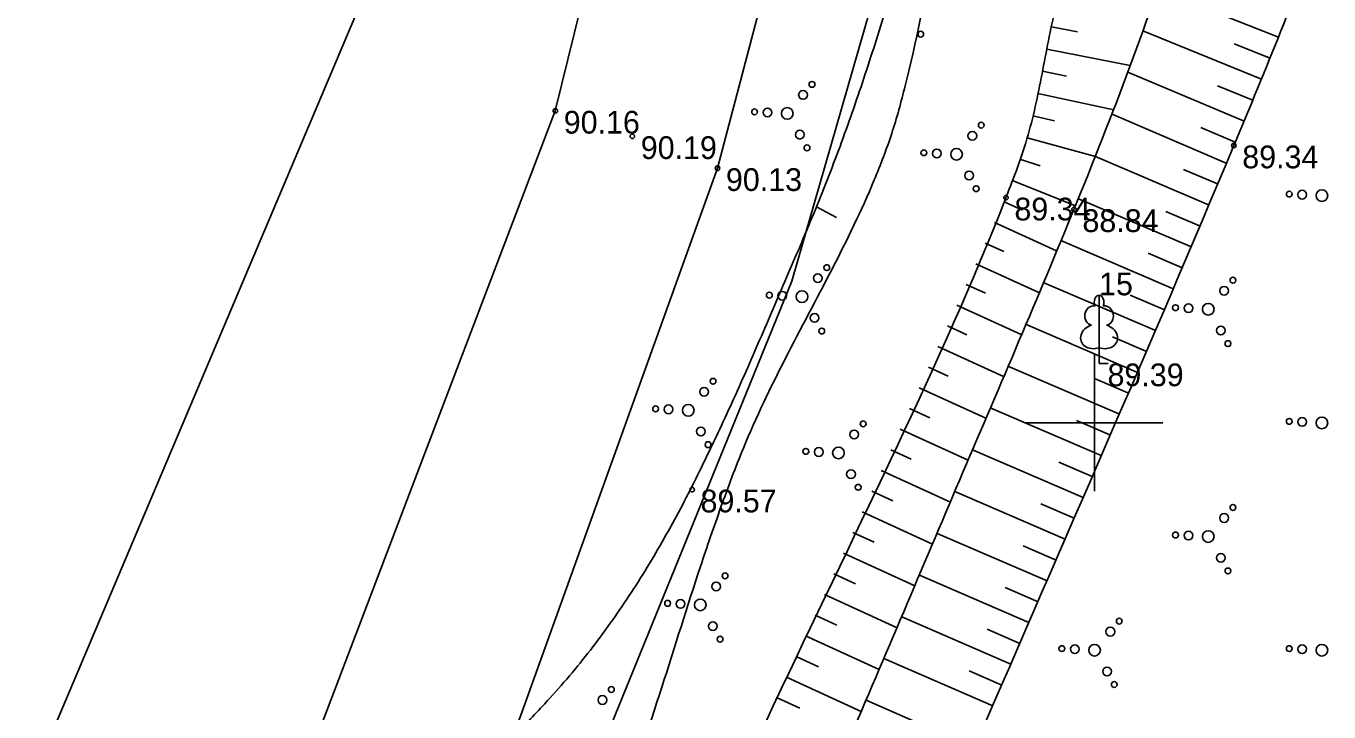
# Model space of a CAD drawing. Extents: x 635228 to 635525, y 248590 to 248800.
# Drawn here: x 635326.51 to 635355.15, y 248693.64 to 248708.73 of the extents above; entities that cross this region are included whole.
import ezdxf

# ---------------------------------------------------------------- set-up
doc = ezdxf.new("R2010")
doc.units = 0
for name, color, linetype in [('CELI_CMAL_####_####_#', 7, 'Continuous'), ('GEOD_ELEM_####_####_#', 7, 'Continuous'), ('RAMI_UZMR_####_####_#', 7, 'Continuous'), ('RELJ_AATZ_####_TKST_#', 7, 'Continuous'), ('RELJ_ELEM_####_####_#', 7, 'Continuous'), ('RELJ_HORZ_PAMT_####_#', 7, 'Continuous'), ('RELJ_HORZ_RESN_####_#', 7, 'Continuous'), ('RELJ_NOGA_####_####_#', 7, 'Continuous'), ('RELJ_NOGL_####_####_#', 7, 'Continuous'), ('ROBZ_PROJ_####_####_#', 7, 'Continuous'), ('ROBZ_UZMR_####_####_#', 7, 'Continuous'), ('TERT_DIAM_####_TKST_#', 7, 'Continuous'), ('TERT_ELEM_####_####_#', 7, 'Continuous'), ('TERT_KONT_####_####_#', 7, 'Continuous')]:
    doc.layers.add(name, color=color, linetype=linetype)

msp = doc.modelspace()

# ---------------------------------------------------------------- linework, layer by layer
at = {"layer": 'CELI_CMAL_####_####_#'}
for points in [[(635327.703, 248680.035), (635336.747, 248691.797), (635341.71, 248705.602), (635344.776, 248717.251), (635350.856, 248738.106), (635354.904, 248753.168), (635356.755, 248761.086), (635356.988, 248762.081)], [(635352.126, 248761.775), (635351.394, 248755.812), (635346.791, 248738.298), (635340.529, 248716.56), (635338.144, 248706.864), (635332.779, 248692.762), (635327.977, 248685.285), (635325.201, 248682.696)]]:
    msp.add_lwpolyline(points, dxfattribs=at)
at = {"layer": 'GEOD_ELEM_####_####_#'}
for p, q in [((635350, 248701.5), (635350, 248700)), ((635348.5, 248700), (635350, 248700)), ((635350, 248700), (635350, 248698.5)), ((635350, 248700), (635351.5, 248700))]:
    msp.add_line(p, q, dxfattribs=at)
at = {"layer": 'RAMI_UZMR_####_####_#'}
msp.add_lwpolyline([(635379.918, 248627.738), (635364.657, 248634.365), (635359.326, 248636.387), (635355.893, 248639.014), (635323.971, 248655.917), (635326.8, 248663.851), (635331.354, 248676.262), (635327.703, 248680.035), (635326.374, 248681.182), (635325.201, 248682.696), (635327.977, 248685.285), (635332.779, 248692.762), (635338.144, 248706.864), (635340.529, 248716.56), (635346.791, 248738.298), (635351.394, 248755.812), (635352.126, 248761.775)], dxfattribs=at)
at = {"layer": 'RELJ_ELEM_####_####_#'}
for centre in [(635338.144, 248706.864), (635339.838, 248706.305), (635353.063, 248706.101), (635341.71, 248705.602), (635348.053, 248704.954), (635349.548, 248704.698), (635349.55, 248704.699), (635341.152, 248698.532)]:
    msp.add_circle(centre, 0.05, dxfattribs=at)
at = {"layer": 'RELJ_HORZ_PAMT_####_#'}
msp.add_spline([(635330.297, 248677.354), (635331.177, 248678.319), (635332.06, 248679.489), (635332.793, 248680.772), (635333.481, 248682.089), (635334.226, 248683.36), (635335.284, 248684.77), (635336.431, 248686.125), (635337.538, 248687.508), (635338.035, 248688.237), (635338.472, 248689.004), (635339.583, 248691.554), (635340.487, 248694.188), (635341.335, 248696.84), (635341.787, 248698.153), (635342.281, 248699.447), (635343.206, 248701.423), (635344.222, 248703.369), (635345.157, 248705.345), (635345.54, 248706.364), (635345.837, 248707.412), (635346.445, 248710.352), (635346.944, 248713.307), (635347.835, 248719.233), (635348.116, 248721.113), (635348.378, 248722.995), (635348.645, 248724.878), (635348.937, 248726.758), (635349.503, 248728.159), (635350.332, 248729.539), (635351.235, 248730.852), (635351.672, 248731.412), (635352.153, 248731.934), (635352.67, 248732.415), (635353.216, 248732.849), (635353.585, 248732.808), (635353.973, 248732.393), (635354.375, 248731.871), (635354.581, 248731.654), (635354.79, 248731.511), (635355.514, 248731.162), (635356.357, 248730.815), (635357.156, 248730.69), (635357.748, 248731.008), (635358.207, 248731.666), (635358.657, 248732.33), (635359.531, 248733.675), (635361.193, 248736.42), (635362.771, 248739.216), (635364.301, 248742.038), (635372.089, 248756.526)], degree=3, dxfattribs=at)
at = {"layer": 'RELJ_HORZ_RESN_####_#'}
msp.add_line((635343.886, 248704.75), (635344.329, 248704.519), dxfattribs=at)
for points in [[(635346.739, 248717.915), (635346.608, 248716.083), (635346.466, 248714.252), (635346.348, 248713.214), (635346.269, 248712.697), (635346.182, 248712.182), (635345.98, 248711.16), (635345.727, 248710.151), (635345.266, 248708.625), (635344.77, 248707.113), (635344.229, 248705.619), (635343.634, 248704.146), (635343.044, 248702.77), (635342.451, 248701.393), (635341.838, 248700.031), (635341.518, 248699.356), (635341.19, 248698.685), (635340.494, 248697.382), (635339.719, 248696.124), (635339.299, 248695.519), (635338.859, 248694.931), (635337.907, 248693.816), (635337.205, 248693.072)], [(635342.967, 248665.189), (635350.649, 248671.097), (635353.044, 248672.199), (635354.147, 248672.641), (635355.27, 248673.022), (635357.544, 248673.711), (635360.916, 248674.993), (635361.461, 248675.281), (635362, 248675.6), (635362.585, 248676.091), (635362.941, 248676.666), (635363.082, 248678.034), (635362.825, 248678.873), (635362.542, 248679.71), (635361.896, 248681.359), (635361.504, 248682.258), (635361.094, 248683.142), (635360.687, 248684.033), (635360.306, 248684.949), (635359.942, 248686.647), (635360.049, 248687.813), (635360.176, 248688.176), (635361.529, 248691.159), (635363.072, 248694.104), (635364.881, 248696.95), (635367.032, 248699.635), (635368.378, 248700.848), (635369.286, 248701.486)]]:
    msp.add_spline(points, degree=3, dxfattribs=at)
at = {"layer": 'RELJ_NOGA_####_####_#'}
for p, q in [((635354.045, 248708.488), (635351.389, 248709.545)), ((635349.053, 248708.715), (635349.623, 248708.599)), ((635353.671, 248707.56), (635351.062, 248708.626)), ((635353.859, 248708.023), (635353.069, 248708.342)), ((635348.954, 248708.225), (635350.785, 248707.863)), ((635348.857, 248707.735), (635349.382, 248707.629)), ((635353.289, 248706.636), (635350.73, 248707.712)), ((635353.481, 248707.097), (635352.705, 248707.417)), ((635348.756, 248707.245), (635350.422, 248706.888)), ((635348.646, 248706.757), (635349.12, 248706.642)), ((635352.898, 248705.715), (635350.385, 248706.79)), ((635348.522, 248706.273), (635350.024, 248705.861)), ((635353.095, 248706.175), (635352.334, 248706.499)), ((635348.378, 248705.794), (635348.807, 248705.652)), ((635352.505, 248704.796), (635350.023, 248705.858)), ((635352.701, 248705.256), (635351.953, 248705.576)), ((635348.209, 248705.323), (635349.582, 248704.778)), ((635348.012, 248704.864), (635348.416, 248704.68)), ((635352.112, 248703.877), (635349.646, 248704.931)), ((635352.308, 248704.336), (635351.567, 248704.653)), ((635347.804, 248704.409), (635349.163, 248703.788)), ((635351.718, 248702.957), (635349.257, 248704.01)), ((635347.596, 248703.955), (635348.008, 248703.767)), ((635351.915, 248703.417), (635351.176, 248703.733)), ((635347.388, 248703.5), (635348.774, 248702.867)), ((635347.181, 248703.045), (635347.6, 248702.853)), ((635351.325, 248702.038), (635348.868, 248703.089)), ((635351.521, 248702.498), (635350.784, 248702.813)), ((635346.973, 248702.59), (635348.385, 248701.945)), ((635346.765, 248702.136), (635347.193, 248701.94)), ((635350.931, 248701.119), (635348.48, 248702.17)), ((635346.557, 248701.681), (635347.996, 248701.023)), ((635351.128, 248701.578), (635350.392, 248701.893)), ((635346.349, 248701.226), (635346.785, 248701.027)), ((635350.537, 248700.199), (635348.091, 248701.248)), ((635350.734, 248700.659), (635350, 248700.974)), ((635346.141, 248700.771), (635347.608, 248700.101)), ((635345.934, 248700.317), (635346.378, 248700.114)), ((635350.143, 248699.28), (635347.703, 248700.328)), ((635350.34, 248699.74), (635349.607, 248700.054)), ((635345.726, 248699.862), (635347.219, 248699.179)), ((635345.518, 248699.407), (635345.97, 248699.2)), ((635349.748, 248698.362), (635347.316, 248699.409)), ((635349.946, 248698.821), (635349.215, 248699.135)), ((635345.31, 248698.952), (635346.83, 248698.258)), ((635345.102, 248698.498), (635345.562, 248698.287)), ((635349.353, 248697.443), (635346.928, 248698.49)), ((635344.894, 248698.043), (635346.44, 248697.336)), ((635349.55, 248697.902), (635348.822, 248698.216)), ((635344.686, 248697.588), (635345.154, 248697.374)), ((635348.956, 248696.525), (635346.538, 248697.568)), ((635344.479, 248697.133), (635346.05, 248696.415)), ((635349.154, 248696.984), (635348.428, 248697.298)), ((635344.271, 248696.679), (635344.746, 248696.461)), ((635348.559, 248695.607), (635346.15, 248696.651)), ((635344.063, 248696.224), (635345.658, 248695.495)), ((635348.758, 248696.066), (635348.034, 248696.379)), ((635343.855, 248695.769), (635344.337, 248695.549)), ((635348.162, 248694.69), (635345.76, 248695.733)), ((635348.361, 248695.148), (635347.639, 248695.461)), ((635343.647, 248695.314), (635345.265, 248694.575)), ((635343.439, 248694.86), (635343.928, 248694.636)), ((635347.763, 248693.773), (635345.368, 248694.815)), ((635347.962, 248694.231), (635347.243, 248694.544)), ((635343.231, 248694.405), (635344.871, 248693.655)), ((635343.023, 248693.95), (635343.518, 248693.724)), ((635347.363, 248692.856), (635344.976, 248693.899))]:
    msp.add_line(p, q, dxfattribs=at)
for points in [[(635375.27, 248754.857), (635369.314, 248744.971), (635367.429, 248741.507), (635365.696, 248737.957), (635363.943, 248734.417), (635363.006, 248732.681), (635362, 248730.984), (635361.355, 248730.103), (635360.628, 248729.283), (635359.885, 248728.474), (635359.193, 248727.625), (635357.58, 248725.368), (635356.018, 248723.079), (635353.089, 248718.349), (635349.569, 248710.638), (635349.163, 248709.221), (635348.864, 248707.772), (635348.539, 248706.335), (635348.053, 248704.954), (635343.12, 248694.162), (635337.407, 248681.667), (635331.093, 248670.147), (635326.8, 248663.851)], [(635326.8, 248663.851), (635325.31, 248661.345), (635325.174, 248660.918), (635325.219, 248660.451), (635325.416, 248659.984), (635325.736, 248659.553), (635326.126, 248659.27), (635326.575, 248659.146), (635327.409, 248659.333), (635327.907, 248659.688), (635328.397, 248660.078), (635328.864, 248660.506), (635329.288, 248660.978), (635331.594, 248663.918), (635332.687, 248665.412), (635333.734, 248666.95), (635337.875, 248673.353), (635341.554, 248680.001), (635347.428, 248693.006), (635353.063, 248706.101), (635354.098, 248708.621), (635355.097, 248711.155), (635356.117, 248713.682), (635356.653, 248714.935), (635357.216, 248716.179), (635358.916, 248719.218), (635360.822, 248722.14), (635362.339, 248724.363), (635363.916, 248726.545), (635365.467, 248728.744), (635366.906, 248731.015), (635368.464, 248733.981), (635369.863, 248737.03), (635371.249, 248740.086), (635372.769, 248743.072), (635378.435, 248753.196)]]:
    msp.add_spline(points, degree=3, dxfattribs=at)
at = {"layer": 'RELJ_NOGL_####_####_#'}
msp.add_spline([(635326.936, 248660.713), (635331.766, 248667.928), (635333.88, 248671.254), (635335.853, 248674.668), (635337.706, 248678.153), (635339.464, 248681.691), (635342.12, 248687.391), (635344.65, 248693.14), (635347.108, 248698.916), (635349.548, 248704.698), (635350.777, 248707.84), (635351.91, 248711.022), (635353.067, 248714.195), (635353.692, 248715.764), (635354.368, 248717.312), (635355.034, 248718.536), (635355.835, 248719.677), (635357.677, 248721.811), (635359.567, 248723.919), (635361.176, 248726.206), (635362.355, 248728.434), (635362.939, 248729.551), (635363.546, 248730.656), (635367.422, 248737.348), (635371.307, 248744.035), (635372.506, 248746.487), (635373.579, 248749.023), (635374.785, 248751.459), (635376.384, 248753.612), (635376.807, 248754.05)], degree=3, dxfattribs=at)
at = {"layer": 'ROBZ_PROJ_####_####_#'}
msp.add_lwpolyline([(635363.321, 248797.676), (635360.888, 248769.918), (635360.483, 248762.615), (635343.343, 248703.12), (635337.46, 248688.66), (635327.79, 248676.828), (635329.653, 248676.366), (635325.542, 248659.74), (635315.4, 248665.602), (635272.581, 248690.35), (635264.056, 248694.511), (635270.042, 248696.015), (635282.096, 248694.845), (635298.597, 248686.068), (635311.236, 248680.45), (635322.498, 248682.379), (635341.086, 248726.313), (635346.481, 248751.583), (635353.471, 248778.803), (635354.805, 248797.676)], dxfattribs=at)
at = {"layer": 'ROBZ_UZMR_####_####_#'}
msp.add_lwpolyline([(635325.542, 248659.74), (635329.653, 248676.366), (635327.79, 248676.828), (635337.46, 248688.66), (635343.343, 248703.12), (635360.483, 248762.615), (635458.607, 248711.134), (635465.459, 248707.539), (635439.457, 248681.038), (635424.543, 248670.014), (635420.979, 248667.379), (635407.07, 248653.18), (635400.067, 248641.149), (635395.162, 248617.539), (635389.031, 248621.062), (635375.858, 248629.115)], close=True, dxfattribs=at)
at = {"layer": 'TERT_ELEM_####_####_#'}
for p, q in [((635350.1, 248701.654), (635350.1, 248701.307)), ((635350.1, 248701.307), (635350.3, 248701.307))]:
    msp.add_line(p, q, dxfattribs=at)
for points in [[(635350.1, 248702.807), (635350.1, 248701.654)], [(635350.19, 248702.575), (635350.189, 248702.576)]]:
    msp.add_lwpolyline(points, dxfattribs=at)
for centre, radius in [((635346.178, 248708.552), 0.064), ((635343.788, 248707.447), 0.064), ((635343.591, 248707.215), 0.096), ((635342.526, 248706.842), 0.064), ((635342.81, 248706.829), 0.096), ((635343.244, 248706.808), 0.128), ((635347.51, 248706.548), 0.064), ((635343.52, 248706.341), 0.096), ((635347.313, 248706.316), 0.096), ((635343.678, 248706.052), 0.064), ((635346.247, 248705.943), 0.064), ((635346.532, 248705.929), 0.096), ((635346.966, 248705.909), 0.128), ((635347.242, 248705.442), 0.096), ((635347.399, 248705.152), 0.064), ((635354.566, 248705.021), 0.096), ((635355, 248705), 0.128), ((635354.282, 248705.034), 0.064), ((635344.112, 248703.416), 0.064), ((635343.915, 248703.185), 0.096), ((635353.044, 248703.139), 0.064), ((635342.85, 248702.811), 0.064), ((635343.134, 248702.798), 0.096), ((635343.568, 248702.777), 0.128), ((635352.848, 248702.908), 0.096), ((635351.782, 248702.534), 0.064), ((635352.066, 248702.521), 0.096), ((635352.5, 248702.5), 0.128), ((635343.844, 248702.31), 0.096), ((635344.002, 248702.021), 0.064), ((635352.776, 248702.033), 0.096), ((635352.934, 248701.744), 0.064), ((635341.612, 248700.916), 0.064), ((635341.415, 248700.685), 0.096), ((635340.35, 248700.311), 0.064), ((635340.634, 248700.298), 0.096), ((635341.068, 248700.277), 0.128), ((635344.914, 248699.979), 0.064), ((635354.282, 248700.034), 0.064), ((635354.566, 248700.021), 0.096), ((635355, 248700), 0.128), ((635341.344, 248699.81), 0.096), ((635344.717, 248699.747), 0.096), ((635341.502, 248699.521), 0.064), ((635343.651, 248699.374), 0.064), ((635343.936, 248699.36), 0.096), ((635344.37, 248699.34), 0.128), ((635344.646, 248698.873), 0.096), ((635344.804, 248698.583), 0.064), ((635352.848, 248697.908), 0.096), ((635353.044, 248698.139), 0.064), ((635351.782, 248697.534), 0.064), ((635352.066, 248697.521), 0.096), ((635352.5, 248697.5), 0.128), ((635352.776, 248697.033), 0.096), ((635352.934, 248696.744), 0.064), ((635341.876, 248696.636), 0.064), ((635341.68, 248696.404), 0.096), ((635340.614, 248696.031), 0.064), ((635340.898, 248696.018), 0.096), ((635341.332, 248695.997), 0.128), ((635350.544, 248695.639), 0.064), ((635341.608, 248695.53), 0.096), ((635350.348, 248695.408), 0.096), ((635341.766, 248695.241), 0.064), ((635349.282, 248695.034), 0.064), ((635349.566, 248695.021), 0.096), ((635350, 248695), 0.128), ((635354.282, 248695.034), 0.064), ((635354.566, 248695.021), 0.096), ((635355, 248695), 0.128), ((635350.276, 248694.533), 0.096), ((635350.434, 248694.244), 0.064), ((635339.18, 248693.904), 0.096), ((635339.376, 248694.136), 0.064)]:
    msp.add_circle(centre, radius, dxfattribs=at)
for centre, major_axis, ratio, start_param, end_param in [((635349.972, 248702.362), (-0.039, -0.212), 0.861323, 3.141593, 6.283185), ((635350.1, 248702.657), (0, -0.15), 0.707107, 3.14537, 5.287485), ((635350.1, 248702.657), (0, -0.15), 0.707107, 0.995701, 3.137816), ((635350.228, 248702.362), (0.039, -0.212), 0.861323, 0, 3.141593), ((635350.01, 248701.9), (0.307, 0.095), 0.814445, 1.570796, 4.752015), ((635350.19, 248701.9), (-0.307, 0.095), 0.814445, 1.531171, 4.712389)]:
    msp.add_ellipse(centre, major_axis=major_axis, ratio=ratio, start_param=start_param, end_param=end_param, dxfattribs=at)
at = {"layer": 'TERT_KONT_####_####_#'}
msp.add_spline([(635347.944, 248675.14), (635353.969, 248676.317), (635361.548, 248680.892), (635362.735, 248687.694), (635367.699, 248695.072), (635365.801, 248699.259), (635373.4, 248711.674), (635374.835, 248703.881), (635382.868, 248697.463), (635386.085, 248703.415)], degree=3, dxfattribs=at)

# ---------------------------------------------------------------- texts
at = {"layer": 'RELJ_AATZ_####_TKST_#'}
for s, p in [(' 90.16', (635338.144, 248706.364)), (' 90.19', (635339.838, 248705.805)), (' 89.34', (635353.063, 248705.601)), (' 90.13', (635341.71, 248705.102)), (' 89.34', (635348.053, 248704.454)), (' 88.84', (635349.548, 248704.198)), (' 88.84', (635349.55, 248704.199)), (' 89.39', (635350.1, 248700.807)), (' 89.57', (635341.152, 248698.032))]:
    msp.add_text(s, height=0.5, dxfattribs=at).set_placement(p)
at = {"layer": 'TERT_DIAM_####_TKST_#'}
msp.add_text('15', height=0.5, dxfattribs=at).set_placement((635350.1, 248702.807))

doc.saveas('drawing.dxf')
